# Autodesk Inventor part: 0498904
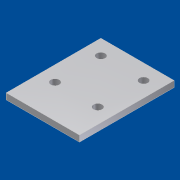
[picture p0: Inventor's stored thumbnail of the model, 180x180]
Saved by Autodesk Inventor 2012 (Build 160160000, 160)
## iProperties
Company: CAD-Verlag
Shininess: 64.0
Length Units: 11269
Angle Units: 11279
Time Units: 11290
Mass Units: 11283
Length Display Precision: 3
Angle Display Precision: 2
Compacted: True
Part Number: 0498904
Document SubType Name: Modeling
Created: 2004-09
Material: Standard
Designer: Greiling
Manufacturer: Standard
Standards Organization: Custom
Density: 1 g/cm^3
Density: 0.0
Volumn: 0.0
Area: 0.0
PropertySet Name: Model Information
Control State: 0
Master: False
Checked Out: False
Author: Jürgen Kronas
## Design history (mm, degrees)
sketch "Skizze1" dims "d11" = 10
  geometry: L1 (0, 124)-(0, -93) reference; L2 (-72, 0)-(96, 0) reference; L3 (-72, 0)-(96, 0) reference; L4 (0, -93)-(0, 124) reference; L5 (-60, 77.5)-(60, 77.5); L6 (60, 77.5)-(60, -77.5); L7 (60, -77.5)-(-60, -77.5); L8 (-60, -77.5)-(-60, 77.5); L9 (-42, 60.5)-(-42, 44.5); L10 (-28, 60.5)-(-28, 44.5); L11 (-28, -14.5)-(-28, -30.5); L12 (-42, -14.5)-(-42, -30.5); L13 (28, -14.5)-(28, -30.5); L14 (42, -14.5)-(42, -30.5); L15 (28, 60.5)-(28, 44.5); L16 (42, 60.5)-(42, 44.5); A1 r 7 centre (-35, 60.5) between (-28, 60.5) and (-42, 60.5); A2 r 7 centre (-35, 44.5) between (-42, 44.5) and (-28, 44.5); A3 r 7 centre (-35, -30.5) between (-42, -30.5) and (-28, -30.5); A4 r 7 centre (-35, -14.5) between (-28, -14.5) and (-42, -14.5); A5 r 7 centre (35, -30.5) between (28, -30.5) and (42, -30.5); A6 r 7 centre (35, -14.5) between (42, -14.5) and (28, -14.5); A7 r 7 centre (35, 60.5) between (42, 60.5) and (28, 60.5); A8 r 7 centre (35, 44.5) between (28, 44.5) and (42, 44.5); 1 further point
  constraints: 24 end point, 16 point on circle, 12 symmetric about line, 8 centre point, 4 parallel, 4 tangent, 1 collinear, 1 horizontal, 1 perpendicular, 1 vertical, 19 other
  dimensions: "d0" = 155 distance of L7.end L5.start; "d1" = 120 distance of L5.start L5.end; "d2" = 14 diameter of A1; "d3" = 14 diameter of A2; "d4" = 16 distance of A2.centre A1.centre; "d5" = 17 distance from line of L5 A1.centre; "d8" = 75 distance of A2.centre A3.centre; "d13" = 70 distance of A7.centre A1.centre
extrude "Extrusion1" new body sketch "Skizze1" distance "d14" = 10; taper "d15" = 0 deg
sketch "Skizze2"
  geometry: L1 (-42, 44.5)-(-42, 60.5) reference; L2 (-28, 60.5)-(-28, 44.5) reference; L3 (-42, -30.5)-(-42, -14.5) reference; L4 (-28, -14.5)-(-28, -30.5) reference; L5 (28, -30.5)-(28, -14.5) reference; L6 (42, -14.5)-(42, -30.5) reference; L7 (28, 44.5)-(28, 60.5) reference; L8 (42, 60.5)-(42, 44.5) reference; L9 (-42, 52.5)-(-28, 52.5); L10 (28, 52.5)-(42, 52.5); L11 (-42, -22.5)-(-28, -22.5); L12 (28, -22.5)-(42, -22.5); 5 further points
  constraints: 12 midpoint, 8 end point
  dimensions: "d25" = 70 distance of point (35, 52.5) point (-35, 52.5) (derived); "d26" = 75 distance of point (-35, -22.5) point (-35, 52.5) (derived)
sketch "Skizze3"
  geometry: L1 (42, 60.5)-(42, 44.5) reference; L2 (28, 44.5)-(28, 60.5) reference; L3 (-28, 60.5)-(-28, 44.5) reference; L4 (-42, 44.5)-(-42, 60.5) reference; L5 (42, -14.5)-(42, -30.5) reference; L6 (28, -30.5)-(28, -14.5) reference; L7 (-28, -14.5)-(-28, -30.5) reference; L8 (-42, -30.5)-(-42, -14.5) reference; L9 (60, 77.5)-(60, -77.5) reference; L10 (-60, 77.5)-(60, 77.5) reference; L11 (-60, -77.5)-(-60, 77.5) reference; L12 (60, -77.5)-(-60, -77.5) reference; A1 r 7 centre (35, 60.5) between (42, 60.5) and (28, 60.5) reference; A2 r 7 centre (35, 44.5) between (28, 44.5) and (42, 44.5) reference; A3 r 7 centre (-35, 44.5) between (-42, 44.5) and (-28, 44.5) reference; A4 r 7 centre (-35, 60.5) between (-28, 60.5) and (-42, 60.5) reference; A5 r 7 centre (35, -14.5) between (42, -14.5) and (28, -14.5) reference; A6 r 7 centre (35, -30.5) between (28, -30.5) and (42, -30.5) reference; A7 r 7 centre (-35, -14.5) between (-28, -14.5) and (-42, -14.5) reference; A8 r 7 centre (-35, -30.5) between (-42, -30.5) and (-28, -30.5) reference; 1 further point
extrude "Extrusion2" join sketch "Skizze3" distance "d16" = 10; taper "d17" = 0 deg
hole "Bohrung1" sketch "Skizze2" diameter "d18" = 14; stored, may be unused: countersink angle "d22" = 90 deg, drill point angle "d24" = 118 deg; dims "d19" = 6, "d20" = 4, "d21" = 2, "d23" = 8
pattern_linear "Rechteckige Anordnung1" dims "d29" = 70, "d32" = 75
node "Volumenkörper1"
node "Volumenkörpern"
node "Oberflächenkörpern"
node "Projizierte Kontur1"
